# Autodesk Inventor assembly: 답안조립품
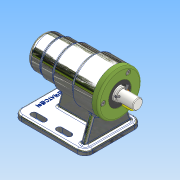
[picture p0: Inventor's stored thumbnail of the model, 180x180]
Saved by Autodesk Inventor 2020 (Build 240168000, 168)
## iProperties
Created: 2021-10
Part Number: 답안조립품
Document SubType Name: Assembly
Designer: user
Author: user
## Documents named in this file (12)
- C:\Users\user\Desktop\711007V1003\답안조립품.iam
- C:\Users\user\Desktop\711007V1003\V벨트풀리.ipt
- C:\Users\user\Desktop\711007V1003\멈춤나사 M3.ipt
- C:\Users\user\Desktop\711007V1003\베어링 6004.ipt
- C:\Users\user\Desktop\711007V1003\베어링 51202.ipt
- C:\Users\user\Desktop\711007V1003\본체.ipt
- C:\Users\user\Desktop\711007V1003\볼트 M4.ipt
- C:\Users\user\Desktop\711007V1003\어댑터슬리브.ipt
- C:\Users\user\Desktop\711007V1003\오일 실 20x35x7.ipt
- C:\Users\user\Desktop\711007V1003\축.ipt
- C:\Users\user\Desktop\711007V1003\커버.ipt
- C:\Users\user\Desktop\711007V1003\키 5x5.ipt
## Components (1 placed, 1 different names)
1. V벨트풀리:1
